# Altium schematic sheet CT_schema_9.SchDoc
size 278 x 170 mm
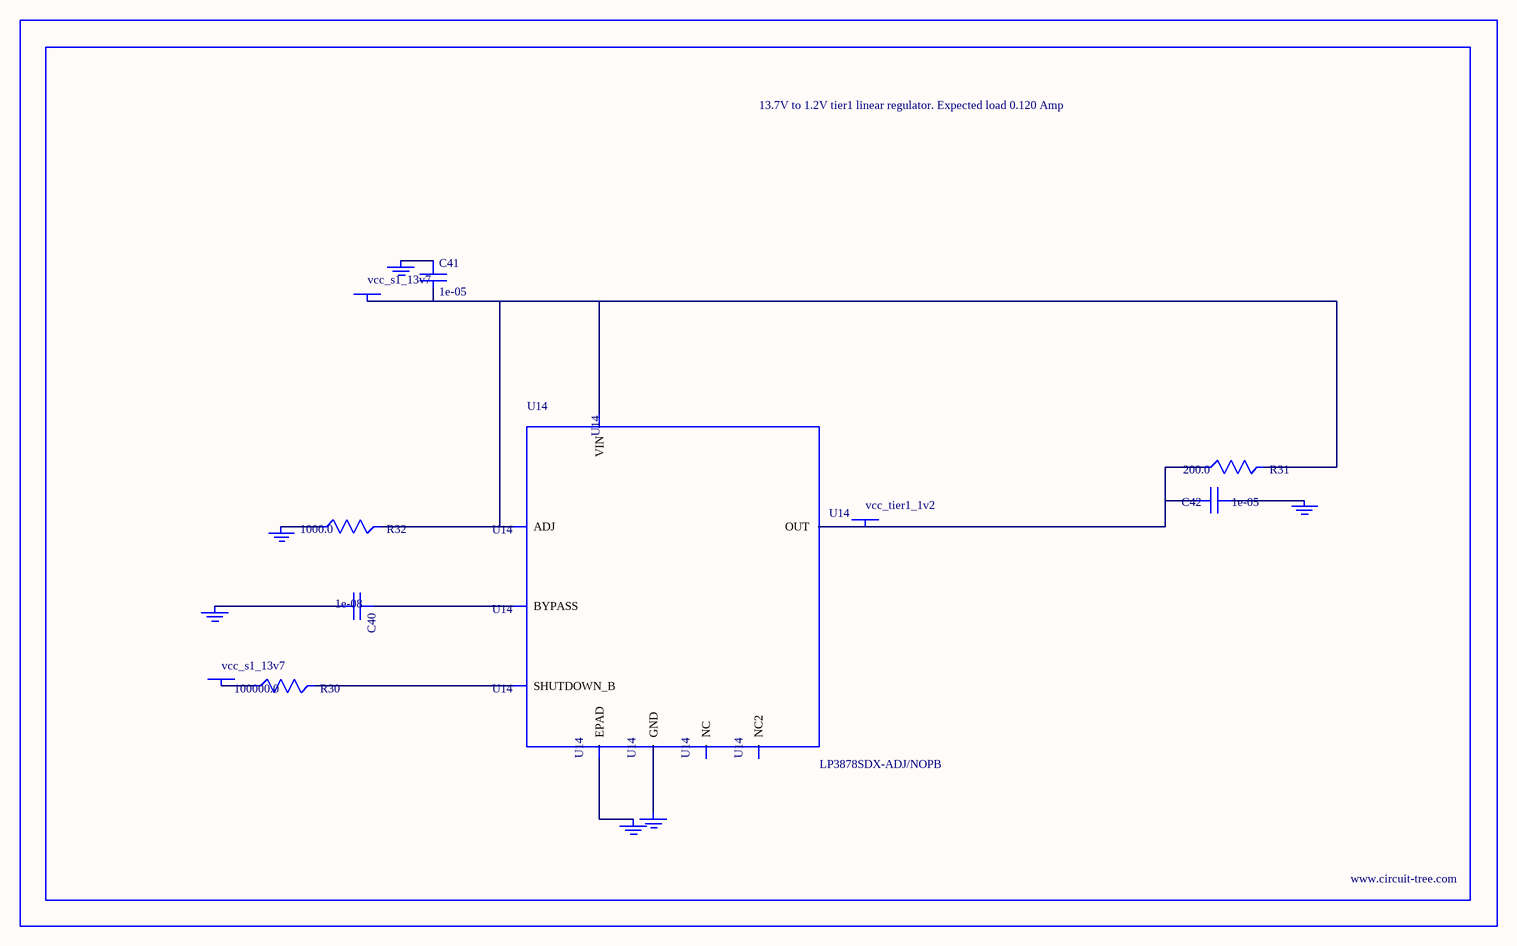
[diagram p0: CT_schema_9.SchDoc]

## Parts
BORDER8  (no value)
C40  1e-08  [C0402]
C41  1e-05  [C1210]
C42  1e-05  [C0805]
GND_INSTANCE_8_0  (no value)
GND_INSTANCE_8_1  (no value)
GND_INSTANCE_8_2  (no value)
GND_INSTANCE_8_3  (no value)
GND_INSTANCE_8_4  (no value)
GND_INSTANCE_8_5  (no value)
POWER_INSTANCE_8_0  vcc_s1_13v7
POWER_INSTANCE_8_1  vcc_s1_13v7
POWER_INSTANCE_8_2  vcc_tier1_1v2
R30  100000.0  [R0603]
R31  200.0  [R0603]
R32  1000.0  [R0603]
U14  LP3878SDX-ADJ/NOPB  [WSON-8]

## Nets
NetC40_1: C40.1 U14.1(BYPASS)
NetC40_2: C40.2 GND_INSTANCE_8_0.0(GND)
NetC41_1: C41.1 GND_INSTANCE_8_1.0(GND)
NetC41_2: C41.2 POWER_INSTANCE_8_0.0(PWR) R31.2 R32.2 U14.4(VIN) U14.6(ADJ)
NetC42_1: C42.1 GND_INSTANCE_8_2.0(GND)
NetC42_2: C42.2 POWER_INSTANCE_8_2.0(PWR) R31.1 U14.5(OUT)
NetGND_INSTANCE_8_3_0: GND_INSTANCE_8_3.0(GND) R32.1
NetGND_INSTANCE_8_4_0: GND_INSTANCE_8_4.0(GND) U14.PAD(EPAD)
NetGND_INSTANCE_8_5_0: GND_INSTANCE_8_5.0(GND) U14.3(GND)
NetPOWER_INSTANCE_8_1_0: POWER_INSTANCE_8_1.0(PWR) R30.1
NetR30_2: R30.2 U14.8(SHUTDOWN_B)

Not connected (* = marked no-connect by the designer): U14 2(NC) 7(NC2)

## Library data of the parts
BORDER8 = BORDER_PAGE8
C40 = C0402C103K3RAC
C41 = C1210C106K5PACTU
C42 = GRM219R60J106ME19D
GND_INSTANCE_8_0-GND_INSTANCE_8_5 = GND
POWER_INSTANCE_8_0-POWER_INSTANCE_8_2 = PWR
R30 = RC0603JR-07100KL
R31 = RC0603JR-07200RL
R32 = RC0603JR-071KL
